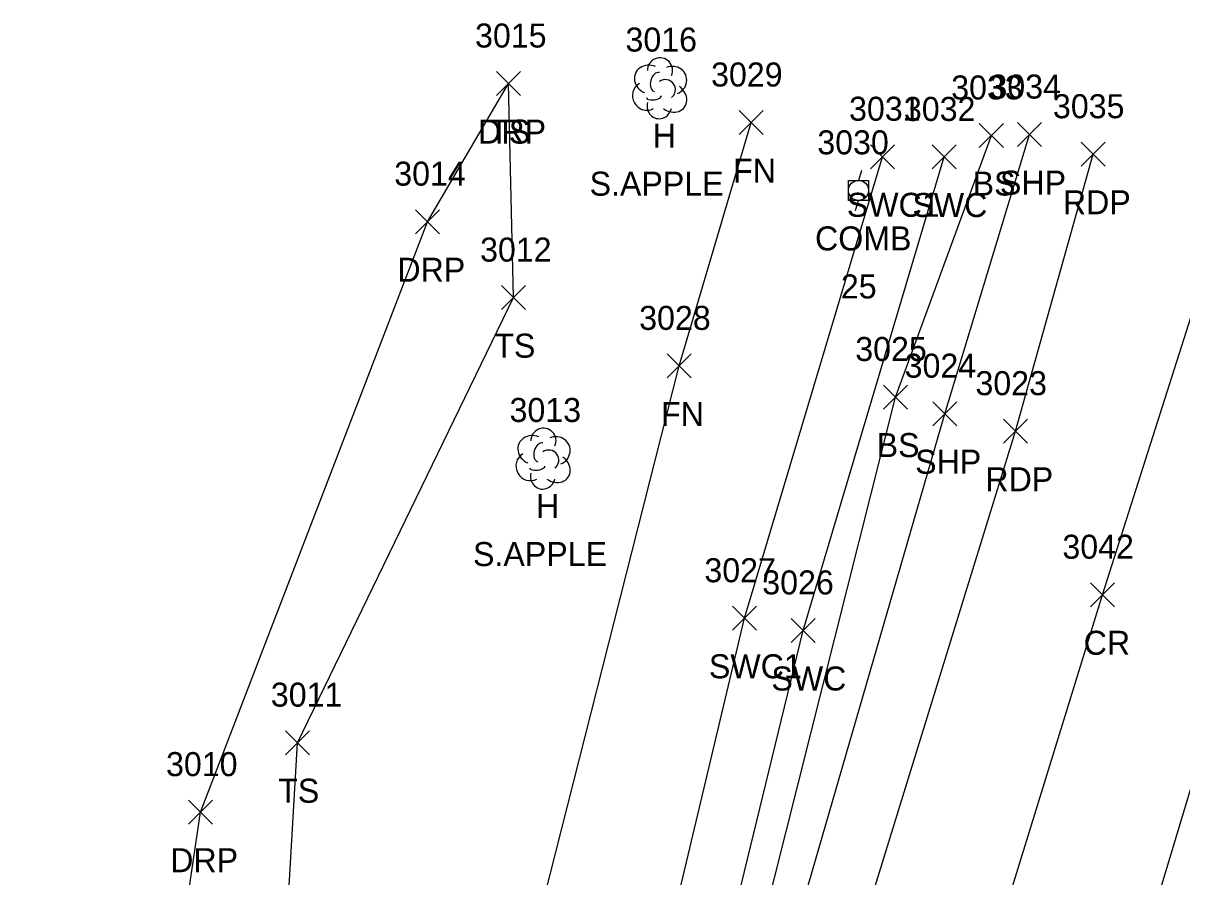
# Model space of a CAD drawing. Extents: x 1477930 to 1480780, y 774090 to 784647.
# Drawn here: x 1479470.3 to 1479566.7, y 775241.7 to 775312.7 of the extents above; entities that cross this region are included whole.
import ezdxf

# ---------------------------------------------------------------- set-up
doc = ezdxf.new("R2010")
doc.units = 0
for name, color, linetype in [('L_A', 7, 'Continuous'), ('L_C', 7, 'Continuous'), ('L_I', 7, 'Continuous'), ('L_TIC', 7, 'Continuous'), ('LELB', 7, 'Continuous'), ('LFNC', 7, 'Continuous'), ('LTD', 7, 'Continuous'), ('P_A', 7, 'Continuous'), ('P_I', 7, 'Continuous'), ('P_TIC', 7, 'Continuous'), ('PET', 7, 'Continuous'), ('PRC', 7, 'Continuous'), ('PSP', 7, 'Continuous'), ('R_A', 7, 'Continuous'), ('R_I', 7, 'Continuous'), ('R_TIC', 7, 'Continuous'), ('RDP', 7, 'Continuous'), ('RSW', 7, 'Continuous'), ('U_A', 7, 'Continuous'), ('U_C', 7, 'Continuous'), ('U_I', 7, 'Continuous'), ('UP', 7, 'Continuous')]:
    doc.layers.add(name, color=color, linetype=linetype)

msp = doc.modelspace()

# ---------------------------------------------------------------- linework, layer by layer
at = {"layer": 'L_TIC'}
for points in [[(1479509.669, 775306.712), (1479511.669, 775308.712)], [(1479511.669, 775306.712), (1479509.669, 775308.712)], [(1479529.888, 775303.466), (1479531.888, 775305.466)], [(1479531.888, 775303.466), (1479529.888, 775305.466)], [(1479549.864, 775302.386), (1479551.864, 775304.386)], [(1479551.864, 775302.386), (1479549.864, 775304.386)], [(1479510.088, 775288.887), (1479512.088, 775290.887)], [(1479512.088, 775288.887), (1479510.088, 775290.887)], [(1479523.895, 775283.2), (1479525.895, 775285.2)], [(1479525.895, 775283.2), (1479523.895, 775285.2)], [(1479541.879, 775280.609), (1479543.879, 775282.609)], [(1479543.879, 775280.609), (1479541.879, 775282.609)], [(1479492.108, 775251.826), (1479494.108, 775253.826)], [(1479494.108, 775251.826), (1479492.108, 775253.826)]]:
    msp.add_lwpolyline(points, dxfattribs=at)
at = {"layer": 'LELB'}
for points in [[(1479498.927, 775210.469), (1479491.547, 775225.637), (1479493.108, 775252.826), (1479511.088, 775289.887), (1479510.669, 775307.712)], [(1479530.802, 775233.534), (1479542.879, 775281.609), (1479550.864, 775303.386)]]:
    msp.add_lwpolyline(points, dxfattribs=at)
at = {"layer": 'LFNC'}
msp.add_lwpolyline([(1479511.216, 775230.261), (1479524.895, 775284.2), (1479530.888, 775304.466)], dxfattribs=at)
at = {"layer": 'LTD'}
for p, q in [((1479523.243, 775307.375), (1479523.243, 775307.375)), ((1479523.243, 775307.375), (1479523.243, 775307.375)), ((1479513.54, 775276.533), (1479513.54, 775276.533)), ((1479513.54, 775276.533), (1479513.54, 775276.533))]:
    msp.add_line(p, q, dxfattribs=at)
for centre in [(1479523.29, 775308.809), (1479513.587, 775277.967)]:
    msp.add_arc(centre, 1.047, 335.52715, 180.95627, dxfattribs=at)
for centre, major_axis, ratio, start_param, end_param in [((1479522.451, 775308.041), (1.21, -0.512), 0.895232, 1.570796, 4.712389), ((1479524.285, 775307.958), (-1.141, -0.483), 0.949671, 1.570796, 4.712389), ((1479523.035, 775307.833), (-0.208, -0.792), 0.645439, 3.141593, 6.283185), ((1479523.743, 775307.208), (-0.5, 0.667), 0.989748, 3.141593, 6.283185), ((1479522.16, 775306.666), (0.584, -1.042), 0.959034, 3.141593, 6.283185), ((1479524.243, 775306.541), (-1.09, 0.792), 0.841452, 1.570796, 4.712389), ((1479523.243, 775305.875), (0.265, 1.061), 0.942809, 1.570796, 4.712389), ((1479522.785, 775306.624), (-0.625, -0.083), 0.423636, 0, 3.141593), ((1479512.749, 775277.2), (1.21, -0.512), 0.895232, 1.570796, 4.712389), ((1479514.582, 775277.117), (-1.141, -0.483), 0.949671, 1.570796, 4.712389), ((1479513.332, 775276.992), (-0.208, -0.792), 0.645439, 3.141593, 6.283185), ((1479514.04, 775276.367), (-0.5, 0.667), 0.989748, 3.141593, 6.283185), ((1479512.457, 775275.825), (0.584, -1.042), 0.959034, 3.141593, 6.283185), ((1479514.541, 775275.7), (-1.09, 0.792), 0.841452, 1.570796, 4.712389), ((1479513.541, 775275.033), (0.265, 1.061), 0.942809, 1.570796, 4.712389), ((1479513.082, 775275.783), (-0.625, -0.083), 0.423636, 0, 3.141593)]:
    msp.add_ellipse(centre, major_axis=major_axis, ratio=ratio, start_param=start_param, end_param=end_param, dxfattribs=at)
at = {"layer": 'P_TIC'}
for points in [[(1479553.044, 775302.462), (1479555.044, 775304.462)], [(1479555.044, 775302.462), (1479553.044, 775304.462)], [(1479558.331, 775300.825), (1479560.331, 775302.825)], [(1479560.331, 775300.825), (1479558.331, 775302.825)], [(1479545.988, 775279.221), (1479547.988, 775281.221)], [(1479547.988, 775279.221), (1479545.988, 775281.221)], [(1479551.879, 775277.763), (1479553.879, 775279.763)], [(1479553.879, 775277.763), (1479551.879, 775279.763)], [(1479559.116, 775264.144), (1479561.116, 775266.144)], [(1479561.116, 775264.144), (1479559.116, 775266.144)]]:
    msp.add_lwpolyline(points, dxfattribs=at)
at = {"layer": 'PET'}
msp.add_lwpolyline([(1479526.816, 775212.315), (1479533.744, 775219.145), (1479539.352, 775234.939), (1479552.879, 775278.763), (1479559.331, 775301.825)], dxfattribs=at)
at = {"layer": 'PRC'}
for points in [[(1479510.934, 775118.308), (1479531.608, 775174.156), (1479544.791, 775215.468), (1479560.116, 775265.144), (1479572.285, 775303.379)], [(1479430.006, 774890.622), (1479468.912, 774957.835), (1479493.209, 775011.919), (1479503.063, 775052.081), (1479530.403, 775123.252), (1479541.538, 775166.063), (1479555.584, 775209.547), (1479571.777, 775263.307), (1479582.904, 775300.166)]]:
    msp.add_lwpolyline(points, dxfattribs=at)
at = {"layer": 'PSP'}
msp.add_lwpolyline([(1479524.067, 775211.585), (1479526.816, 775212.315), (1479529.434, 775220.698), (1479534.247, 775236.24), (1479546.988, 775280.221), (1479554.044, 775303.462)], dxfattribs=at)
at = {"layer": 'R_TIC'}
for points in [[(1479509.669, 775306.712), (1479511.669, 775308.712)], [(1479511.669, 775306.712), (1479509.669, 775308.712)], [(1479540.794, 775300.616), (1479542.794, 775302.616)], [(1479542.794, 775300.616), (1479540.794, 775302.616)], [(1479545.928, 775300.598), (1479547.928, 775302.598)], [(1479547.928, 775300.598), (1479545.928, 775302.598)], [(1479502.945, 775295.21), (1479504.945, 775297.21)], [(1479504.945, 775295.21), (1479502.945, 775297.21)], [(1479529.323, 775262.187), (1479531.323, 775264.187)], [(1479531.323, 775262.187), (1479529.323, 775264.187)], [(1479534.196, 775261.171), (1479536.196, 775263.171)], [(1479536.196, 775261.171), (1479534.196, 775263.171)], [(1479484.038, 775246.041), (1479486.038, 775248.041)], [(1479486.038, 775246.041), (1479484.038, 775248.041)]]:
    msp.add_lwpolyline(points, dxfattribs=at)
at = {"layer": 'RDP'}
msp.add_lwpolyline([(1479483.395, 775235.764), (1479485.038, 775247.041), (1479503.945, 775296.21), (1479510.669, 775307.712)], dxfattribs=at)
at = {"layer": 'RSW'}
for points in [[(1479519.178, 775212.367), (1479522.93, 775232.145), (1479530.323, 775263.187), (1479541.794, 775301.616)], [(1479519.178, 775212.367), (1479524.067, 775211.585), (1479527.75, 775231.484), (1479535.196, 775262.171), (1479546.928, 775301.598)]]:
    msp.add_lwpolyline(points, dxfattribs=at)
at = {"layer": 'UP'}
for p, q in [((1479540.056, 775300.483), (1479539.806, 775299.65)), ((1479538.973, 775297.983), (1479538.973, 775299.65)), ((1479538.973, 775299.65), (1479540.64, 775299.65)), ((1479540.64, 775299.65), (1479540.64, 775297.983)), ((1479539.806, 775298.817), (1479539.806, 775298.817)), ((1479540.64, 775297.983), (1479538.973, 775297.983)), ((1479539.556, 775297.15), (1479539.806, 775297.983))]:
    msp.add_line(p, q, dxfattribs=at)
msp.add_circle((1479539.806, 775298.817), 0.833, dxfattribs=at)

# ---------------------------------------------------------------- texts
at = {"layer": 'L_A'}
for s, p in [('TS', (1479509.078, 775302.712)), ('H', (1479522.676, 775302.375)), ('FN', (1479529.369, 775299.466)), ('BS', (1479549.305, 775298.386)), ('TS', (1479509.498, 775284.887)), ('FN', (1479523.375, 775279.2)), ('BS', (1479541.32, 775276.609)), ('H', (1479512.974, 775271.533)), ('TS', (1479491.517, 775247.826))]:
    msp.add_text(s, height=2, dxfattribs=at).set_placement(p)
at = {"layer": 'L_C'}
for p in [(1479517.432, 775298.375), (1479507.729, 775267.533)]:
    msp.add_text('S.APPLE', height=2, dxfattribs=at).set_placement(p)
at = {"layer": 'L_I'}
for s, p in [('3015', (1479507.897, 775310.712)), ('3016', (1479520.416, 775310.375)), ('3029', (1479527.542, 775307.466)), ('3033', (1479547.525, 775306.386)), ('3012', (1479508.316, 775292.887)), ('3028', (1479521.556, 775287.2)), ('3025', (1479539.54, 775284.609)), ('3013', (1479510.769, 775279.533)), ('3011', (1479490.903, 775255.826))]:
    msp.add_text(s, height=2, dxfattribs=at).set_placement(p)
at = {"layer": 'P_A'}
for s, p in [('SHP', (1479551.58, 775298.462)), ('RDP', (1479556.819, 775296.825)), ('SHP', (1479544.524, 775275.221)), ('RDP', (1479550.368, 775273.763)), ('CR', (1479558.549, 775260.144))]:
    msp.add_text(s, height=2, dxfattribs=at).set_placement(p)
at = {"layer": 'P_I'}
for s, p in [('3034', (1479550.705, 775306.462)), ('3035', (1479555.992, 775304.825)), ('3024', (1479543.65, 775283.221)), ('3023', (1479549.541, 775281.763)), ('3042', (1479556.777, 775268.144))]:
    msp.add_text(s, height=2, dxfattribs=at).set_placement(p)
at = {"layer": 'R_A'}
for s, p in [('DRP', (1479508.157, 775302.712)), ('SWC1', (1479538.834, 775296.616)), ('SWC', (1479544.29, 775296.598)), ('DRP', (1479501.434, 775291.21)), ('SWC1', (1479527.362, 775258.187)), ('SWC', (1479532.558, 775257.171)), ('DRP', (1479482.526, 775242.041))]:
    msp.add_text(s, height=2, dxfattribs=at).set_placement(p)
at = {"layer": 'R_I'}
for s, p in [('3015', (1479507.897, 775310.712)), ('3031', (1479539.023, 775304.616)), ('3032', (1479543.59, 775304.598)), ('3014', (1479501.174, 775299.21)), ('3027', (1479526.984, 775266.187)), ('3026', (1479531.802, 775265.171)), ('3010', (1479482.18, 775250.041))]:
    msp.add_text(s, height=2, dxfattribs=at).set_placement(p)
at = {"layer": 'U_A'}
msp.add_text('COMB', height=2, dxfattribs=at).set_placement((1479536.192, 775293.817))
at = {"layer": 'U_C'}
msp.add_text('25', height=2, dxfattribs=at).set_placement((1479538.342, 775289.817))
at = {"layer": 'U_I'}
msp.add_text('3030', height=2, dxfattribs=at).set_placement((1479536.381, 775301.817))

doc.saveas('drawing.dxf')
